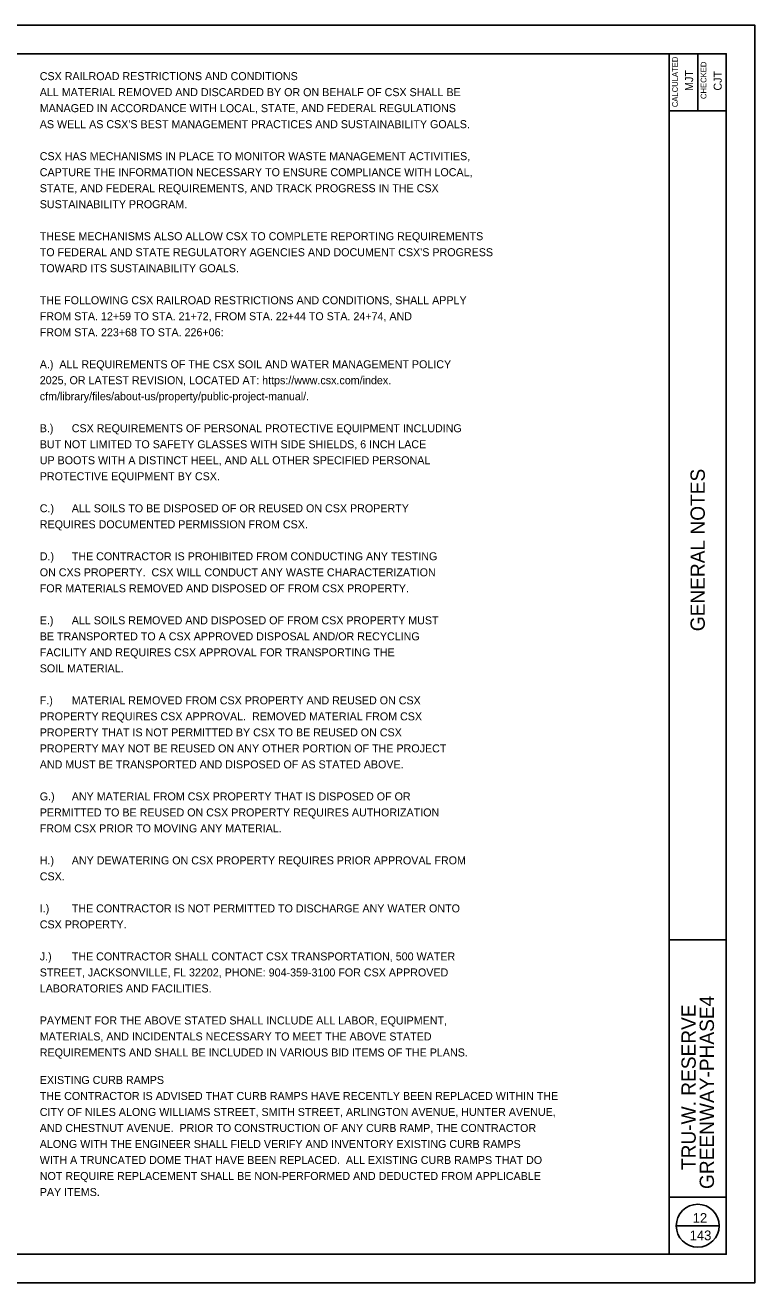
# Model space of a CAD drawing. Extents: x -16 to 195, y -13 to 9.
# Drawn here: x 137.56 to 150.33, y -12.91 to 9.09 of the extents above; entities that cross this region are included whole.
import ezdxf

# ---------------------------------------------------------------- set-up
doc = ezdxf.new("R2010")
doc.units = 0
for name, color, linetype in [('SH_Border', 7, 'Continuous'), ('SH_Cut_Line', 7, 'Continuous'), ('SH_Data', 7, 'Continuous'), ('TX_P_1', 7, 'Continuous')]:
    doc.layers.add(name, color=color, linetype=linetype)

msp = doc.modelspace()

# ---------------------------------------------------------------- linework, layer by layer
at = {"layer": 'SH_Border'}
for p, q in [((148.826, -12.407), (148.826, 8.593)), ((149.326, 8.593), (149.326, 7.593)), ((148.826, 7.593), (149.826, 7.593)), ((148.826, -6.907), (149.826, -6.907)), ((148.826, -11.407), (149.826, -11.407))]:
    msp.add_line(p, q, dxfattribs=at)
msp.add_lwpolyline([(118.326, 8.593), (149.826, 8.593), (149.826, -12.407), (118.326, -12.407)], close=True, dxfattribs=at)
at = {"layer": 'SH_Cut_Line'}
msp.add_lwpolyline([(116.326, -12.907), (150.326, -12.907), (150.326, 9.093), (116.326, 9.093)], close=True, dxfattribs=at)
at = {"layer": 'SH_Data'}
msp.add_line((148.951, -11.907), (149.701, -11.907), dxfattribs=at)
msp.add_circle((149.326, -11.907), 0.375, dxfattribs=at)

# ---------------------------------------------------------------- texts
for s, height, p in [('CALCULATED', 0.1, (148.979, 7.658)), ('CHECKED', 0.1, (149.479, 7.801)), ('MJT', 0.14, (149.246, 7.942)), ('CJT', 0.14, (149.746, 7.949)), ('GENERAL NOTES', 0.25, (149.451, -1.509)), ('GREENWAY-PHASE4', 0.25, (149.611, -11.266)), ('TRU-W. RESERVE', 0.25, (149.292, -10.934))]:
    msp.add_text(s, height=height, rotation=90, dxfattribs=at).set_placement(p)
for s, p in [('12', (149.239, -11.857)), ('143', (149.186, -12.162))]:
    msp.add_text(s, height=0.17, dxfattribs=at).set_placement(p)
at = {"layer": 'TX_P_1'}
for s, p in [('CSX RAILROAD RESTRICTIONS AND CONDITIONS', (137.814, 8.131)), ('ALL MATERIAL REMOVED AND DISCARDED BY OR ON BEHALF OF CSX SHALL BE', (137.814, 7.851)), ('MANAGED IN ACCORDANCE WITH LOCAL, STATE, AND FEDERAL REGULATIONS', (137.814, 7.571)), ("AS WELL AS CSX'S BEST MANAGEMENT PRACTICES AND SUSTAINABILITY GOALS.", (137.814, 7.291)), ('CSX HAS MECHANISMS IN PLACE TO MONITOR WASTE MANAGEMENT ACTIVITIES,', (137.814, 6.731)), ('CAPTURE THE INFORMATION NECESSARY TO ENSURE COMPLIANCE WITH LOCAL,', (137.814, 6.451)), ('STATE, AND FEDERAL REQUIREMENTS, AND TRACK PROGRESS IN THE CSX', (137.814, 6.171)), ('SUSTAINABILITY PROGRAM.', (137.814, 5.891)), ('THESE MECHANISMS ALSO ALLOW CSX TO COMPLETE REPORTING REQUIREMENTS', (137.814, 5.331)), ("TO FEDERAL AND STATE REGULATORY AGENCIES AND DOCUMENT CSX'S PROGRESS", (137.814, 5.051)), ('TOWARD ITS SUSTAINABILITY GOALS.', (137.814, 4.771)), ('THE FOLLOWING CSX RAILROAD RESTRICTIONS AND CONDITIONS, SHALL APPLY', (137.814, 4.211)), ('FROM STA. 12+59 TO STA. 21+72, FROM STA. 22+44 TO STA. 24+74, AND', (137.814, 3.931)), ('FROM STA. 223+68 TO STA. 226+06:', (137.814, 3.651)), ('A.)  ALL REQUIREMENTS OF THE CSX SOIL AND WATER MANAGEMENT POLICY', (137.814, 3.091)), ('2025, OR LATEST REVISION, LOCATED AT: https://www.csx.com/index.', (137.814, 2.812)), ('cfm/library/files/about-us/property/public-project-manual/.', (137.814, 2.532)), ('B.)', (137.814, 1.972)), ('CSX REQUIREMENTS OF PERSONAL PROTECTIVE EQUIPMENT INCLUDING', (138.374, 1.972)), ('BUT NOT LIMITED TO SAFETY GLASSES WITH SIDE SHIELDS, 6 INCH LACE', (137.814, 1.692)), ('UP BOOTS WITH A DISTINCT HEEL, AND ALL OTHER SPECIFIED PERSONAL', (137.814, 1.412)), ('PROTECTIVE EQUIPMENT BY CSX.', (137.814, 1.132)), ('C.)', (137.814, 0.572)), ('ALL SOILS TO BE DISPOSED OF OR REUSED ON CSX PROPERTY ', (138.374, 0.572)), ('REQUIRES DOCUMENTED PERMISSION FROM CSX.', (137.814, 0.292)), ('D.)', (137.814, -0.268)), ('THE CONTRACTOR IS PROHIBITED FROM CONDUCTING ANY TESTING', (138.374, -0.268)), ('ON CXS PROPERTY.  CSX WILL CONDUCT ANY WASTE CHARACTERIZATION', (137.814, -0.548)), ('FOR MATERIALS REMOVED AND DISPOSED OF FROM CSX PROPERTY.', (137.814, -0.828)), ('E.)', (137.814, -1.388)), ('ALL SOILS REMOVED AND DISPOSED OF FROM CSX PROPERTY MUST', (138.374, -1.388)), ('BE TRANSPORTED TO A CSX APPROVED DISPOSAL AND/OR RECYCLING', (137.814, -1.668)), ('FACILITY AND REQUIRES CSX APPROVAL FOR TRANSPORTING THE', (137.814, -1.948)), ('SOIL MATERIAL.', (137.814, -2.228)), ('F.)', (137.814, -2.788)), ('MATERIAL REMOVED FROM CSX PROPERTY AND REUSED ON CSX', (138.374, -2.788)), ('PROPERTY REQUIRES CSX APPROVAL.  REMOVED MATERIAL FROM CSX', (137.814, -3.068)), ('PROPERTY THAT IS NOT PERMITTED BY CSX TO BE REUSED ON CSX', (137.814, -3.348)), ('PROPERTY MAY NOT BE REUSED ON ANY OTHER PORTION OF THE PROJECT ', (137.814, -3.628)), ('AND MUST BE TRANSPORTED AND DISPOSED OF AS STATED ABOVE.', (137.814, -3.908)), ('G.)', (137.814, -4.468)), ('ANY MATERIAL FROM CSX PROPERTY THAT IS DISPOSED OF OR', (138.374, -4.468)), ('PERMITTED TO BE REUSED ON CSX PROPERTY REQUIRES AUTHORIZATION', (137.814, -4.748)), ('FROM CSX PRIOR TO MOVING ANY MATERIAL.', (137.814, -5.027)), ('H.)', (137.814, -5.587)), ('ANY DEWATERING ON CSX PROPERTY REQUIRES PRIOR APPROVAL FROM', (138.374, -5.587)), ('CSX.  ', (137.814, -5.867)), ('I.)', (137.814, -6.427)), ('THE CONTRACTOR IS NOT PERMITTED TO DISCHARGE ANY WATER ONTO', (138.374, -6.427)), ('CSX PROPERTY.', (137.814, -6.707)), ('J.)', (137.814, -7.267)), ('THE CONTRACTOR SHALL CONTACT CSX TRANSPORTATION, 500 WATER', (138.374, -7.267)), ('STREET, JACKSONVILLE, FL 32202, PHONE: 904-359-3100 FOR CSX APPROVED', (137.814, -7.547)), ('LABORATORIES AND FACILITIES.', (137.814, -7.827)), ('PAYMENT FOR THE ABOVE STATED SHALL INCLUDE ALL LABOR, EQUIPMENT, ', (137.814, -8.387)), ('MATERIALS, AND INCIDENTALS NECESSARY TO MEET THE ABOVE STATED', (137.814, -8.667)), ('REQUIREMENTS AND SHALL BE INCLUDED IN VARIOUS BID ITEMS OF THE PLANS.', (137.814, -8.947)), ('EXISTING CURB RAMPS', (137.814, -9.428)), ('THE CONTRACTOR IS ADVISED THAT CURB RAMPS HAVE RECENTLY BEEN REPLACED WITHIN THE', (137.814, -9.708)), ('CITY OF NILES ALONG WILLIAMS STREET, SMITH STREET, ARLINGTON AVENUE, HUNTER AVENUE,', (137.814, -9.988)), ('AND CHESTNUT AVENUE.  PRIOR TO CONSTRUCTION OF ANY CURB RAMP, THE CONTRACTOR', (137.814, -10.268)), ('ALONG WITH THE ENGINEER SHALL FIELD VERIFY AND INVENTORY EXISTING CURB RAMPS', (137.814, -10.548)), ('WITH A TRUNCATED DOME THAT HAVE BEEN REPLACED.  ALL EXISTING CURB RAMPS THAT DO', (137.814, -10.828)), ('NOT REQUIRE REPLACEMENT SHALL BE NON-PERFORMED AND DEDUCTED FROM APPLICABLE', (137.814, -11.108)), ('PAY ITEMS.', (137.814, -11.388))]:
    msp.add_text(s, height=0.14, dxfattribs=at).set_placement(p)

doc.saveas('drawing.dxf')
